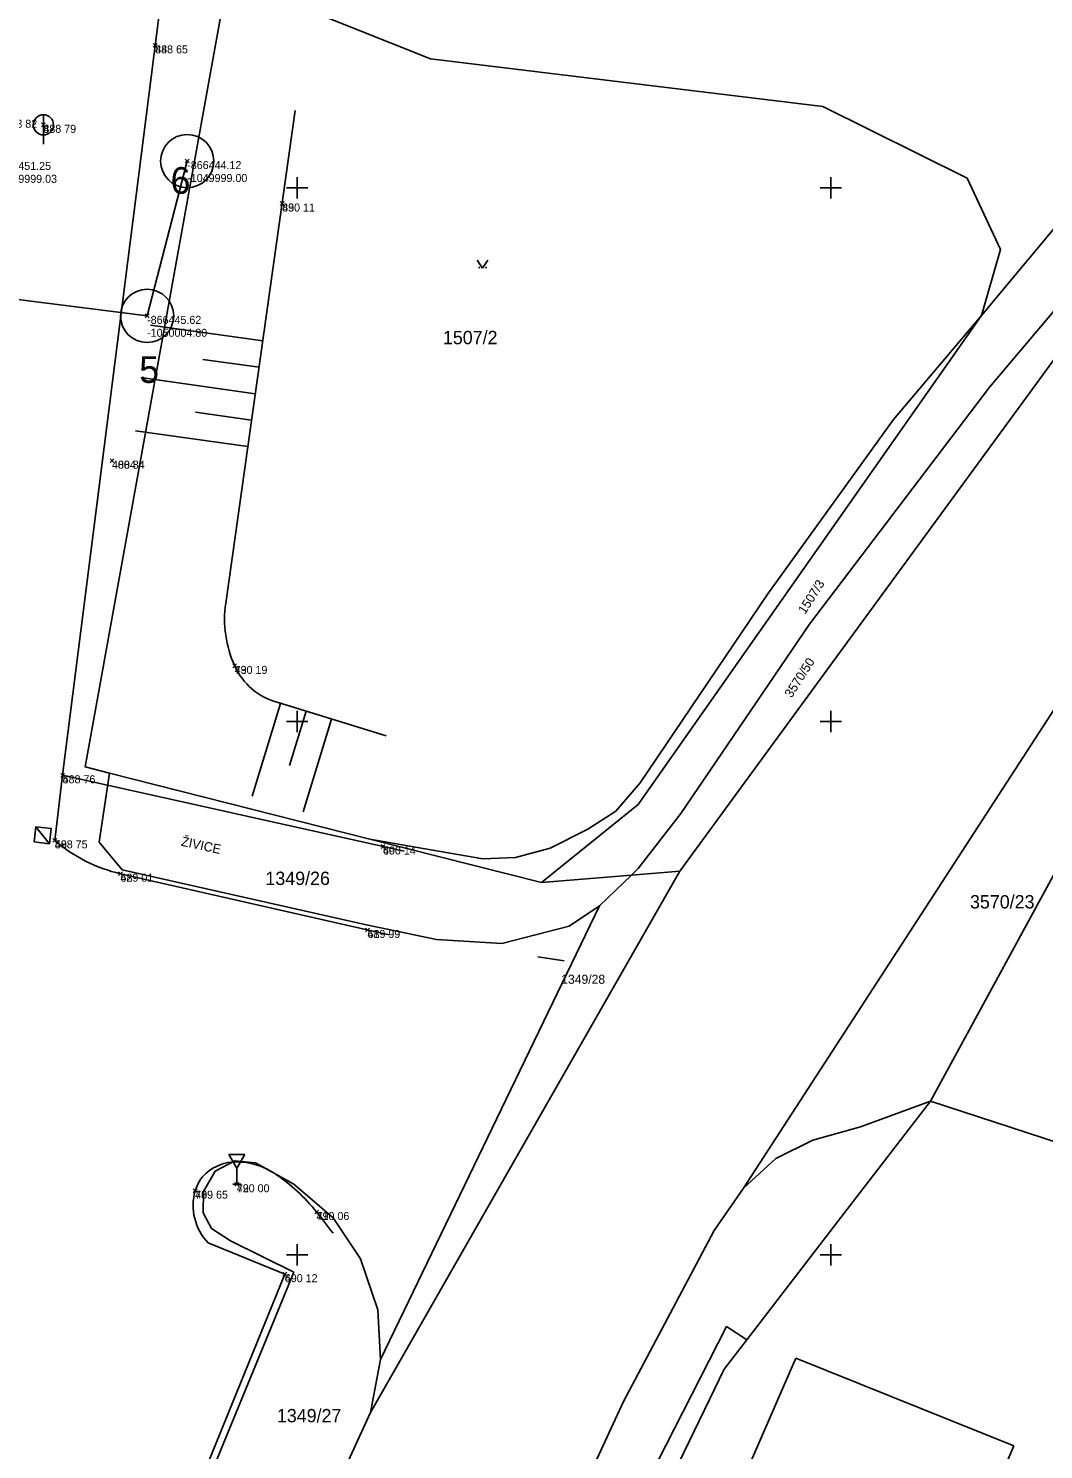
# Model space of a CAD drawing. Extents: x -866624 to -866276, y -1050208 to -1049940.
# Drawn here: x -866450.1 to -866412, y -1050047.3 to -1049994 of the extents above; entities that cross this region are included whole.
import ezdxf

# ---------------------------------------------------------------- set-up
doc = ezdxf.new("R2010")
doc.units = 0
for name, color, linetype in [('00_BODY VYTYČ', 7, 'Continuous'), ('00_POMOCNÉ KCE', 7, 'Continuous'), ('_FORMATY', 7, 'Continuous'), ('bod-cislo', 7, 'Continuous'), ('bod-oznac', 7, 'Continuous'), ('bod-vyska', 7, 'Continuous'), ('CTV-SIT', 7, 'Continuous'), ('Default', 7, 'Continuous'), ('DOPR-ZAR', 7, 'Continuous'), ('HRAN-LIN', 7, 'Continuous'), ('Hranice', 7, 'Continuous'), ('Hranice-budov', 7, 'Continuous'), ('Parcela-pozemkova', 7, 'Continuous'), ('Parcelni-cisla-pomocna', 7, 'Continuous'), ('POTR-ZAR', 7, 'Continuous'), ('SIT_05_NÁVRH PLYN', 7, 'Continuous'), ('TEXT', 7, 'Continuous'), ('VYS-SRAF', 7, 'Continuous'), ('Znacky-kultury', 7, 'Continuous')]:
    doc.layers.add(name, color=color, linetype=linetype)

# ---------------------------------------------------------------- blocks, each defined once
blk = doc.blocks.new('p_park')
at = {"layer": 'Default'}
for p, q in [((-1, 1.5), (0, 0)), ((0, 0), (1, 1.5))]:
    blk.add_line(p, q, dxfattribs=at)
for centre, start, end in [((-0.62, 0.1), 360, 180), ((-0.62, 0.1), 180, 360), ((0.66, 0.1), 0, 180), ((0.66, 0.1), 180, 0)]:
    blk.add_arc(centre, 0.05, start, end, dxfattribs=at)
blk = doc.blocks.new('POINT_DISPLAY')
at = {"layer": 'Default'}
for p, q in [((-0.071, 0.071), (0.071, -0.071)), ((0.071, 0.071), (-0.071, -0.071))]:
    blk.add_line(p, q, dxfattribs=at)
blk = doc.blocks.new('200RS')
at = {"layer": 'POTR-ZAR'}
blk.add_line((0, -0.378), (0, 0.721), dxfattribs=at)
blk.add_circle((0, 0), 0.378, dxfattribs=at)
blk = doc.blocks.new('200DZ')
at = {"layer": 'DOPR-ZAR'}
for p, q in [((-0.149, 0), (0.149, 0)), ((0, -0.599), (0, 0)), ((-0.3, -1.119), (0, -0.599)), ((0, -0.599), (0.3, -1.119)), ((0, -1.119), (-0.3, -1.119)), ((0.3, -1.119), (0, -1.119))]:
    blk.add_line(p, q, dxfattribs=at)
blk = doc.blocks.new('200UV')
at = {"layer": 'POTR-ZAR'}
for p, q in [((-0.288, 0.288), (0.288, -0.288)), ((0.288, 0.288), (-0.288, 0.288)), ((-0.288, 0.288), (-0.288, -0.288)), ((0.288, -0.288), (0.288, 0.288)), ((-0.288, -0.288), (0.288, -0.288))]:
    blk.add_line(p, q, dxfattribs=at)
blk.add_lwpolyline([(0.288, -0.288), (0.288, 0.288), (-0.288, 0.288)], close=True, dxfattribs=at)
blk = doc.blocks.new('CTVSIT')
at = {"layer": 'Default'}
for p, q in [((-2, 0), (2, 0)), ((0, 2), (0, -2))]:
    blk.add_line(p, q, dxfattribs=at)
blk = doc.blocks.new('vytyčení')
at = {"layer": '00_POMOCNÉ KCE'}
for centre in [(-866082.454, -1050060.072), (-866076.494, -1050060.691)]:
    blk.add_circle(centre, 0.998, dxfattribs=at)
at = {"layer": 'SIT_05_NÁVRH PLYN'}
blk.add_lwpolyline([(-866082.454, -1050060.072), (-866076.494, -1050060.691), (-866076.292, -1050069.077)], dxfattribs=at)

msp = doc.modelspace()

# ---------------------------------------------------------------- linework, layer by layer
at = {"layer": '_FORMATY'}
msp.add_line((-866429.993, -1050028.98), (-866430.982, -1050028.83), dxfattribs=at)
at = {"layer": 'HRAN-LIN'}
for p, q in [((-866445.172, -1049993.49), (-866448.79, -1050022.02)), ((-866448.79, -1050022.02), (-866449.08, -1050024.46)), ((-866435.988, -1050024.866), (-866448.79, -1050022.02)), ((-866444.8, -1050051.37), (-866440.46, -1050040.72))]:
    msp.add_line(p, q, dxfattribs=at)
for points in [[(-866440.067, -1049997.099), (-866442.677, -1050015.573)], [(-866440.752, -1050019.284), (-866436.662, -1050020.539)], [(-866436.55, -1050028.005), (-866446.62, -1050025.71)], [(-866443.331, -1050039.55), (-866440.46, -1050040.72)]]:
    msp.add_lwpolyline(points, dxfattribs=at)
for centre, radius, start, end in [((-866438.471, -1050016.167), 4.248, 171.9578, 204.3767), ((-866440.08, -1050016.896), 2.481, 204.3767, 254.2803), ((-866445.362, -1050020.188), 5.663, 228.9634, 257.1636), ((-866442.291, -1050038.193), 1.682, 90.054, 131.4076), ((-866442.291, -1050039.129), 2.617, 56.3463, 90.054), ((-866442.485, -1050037.974), 1.389, 131.4076, 163.9666), ((-866444.667, -1050042.698), 6.906, 38.5998, 56.3463), ((-866441.881, -1050038.147), 2.017, 163.9666, 224.0612), ((-866467.78, -1050061.149), 36.48, 37.0215, 38.5998)]:
    msp.add_arc(centre, radius, start, end, dxfattribs=at)
at = {"layer": 'Hranice'}
for p, q in [((-866447.95, -1050021.71), (-866442.6, -1049992.13)), ((-866442.6, -1049992.13), (-866435, -1049995.17)), ((-866425.65, -1050025.61), (-866402.57, -1049994.04)), ((-866435, -1049995.17), (-866420.29, -1049996.95)), ((-866406.93, -1049995.89), (-866414.35, -1050004.79)), ((-866420.29, -1049996.95), (-866414.88, -1049999.64)), ((-866414.88, -1049999.64), (-866413.64, -1050002.31)), ((-866408.09, -1050000.42), (-866414.04, -1050007.46)), ((-866414.35, -1050004.79), (-866413.64, -1050002.31)), ((-866427.22, -1050023.12), (-866414.35, -1050004.79)), ((-866417.65, -1050008.69), (-866414.35, -1050004.79)), ((-866414.04, -1050007.46), (-866420.79, -1050016.36)), ((-866422.35, -1050015.22), (-866417.65, -1050008.69)), ((-866427.14, -1050022.31), (-866422.35, -1050015.22)), ((-866420.79, -1050016.36), (-866425.62, -1050023.45)), ((-866423.27, -1050037.5), (-866409.54, -1050016.33)), ((-866447.03, -1050021.94), (-866447.95, -1050021.71)), ((-866447.03, -1050021.94), (-866447.42, -1050024.53)), ((-866437.27, -1050024.41), (-866447.03, -1050021.94)), ((-866428.05, -1050023.37), (-866427.14, -1050022.31)), ((-866430.84, -1050026.04), (-866427.22, -1050023.12)), ((-866429.1, -1050024.04), (-866428.05, -1050023.37)), ((-866427.22, -1050025.52), (-866425.62, -1050023.45)), ((-866410.49, -1050023.63), (-866416.26, -1050034.23)), ((-866437.27, -1050024.41), (-866435.56, -1050024.71)), ((-866437.27, -1050024.41), (-866430.84, -1050026.04)), ((-866430.52, -1050024.75), (-866429.1, -1050024.04)), ((-866446.56, -1050025.56), (-866447.42, -1050024.53)), ((-866435.56, -1050024.71), (-866433.04, -1050025.15)), ((-866431.81, -1050025.1), (-866430.52, -1050024.75)), ((-866437.46, -1050027.61), (-866446.56, -1050025.56)), ((-866433.04, -1050025.15), (-866431.81, -1050025.1)), ((-866427.47, -1050025.76), (-866427.22, -1050025.52)), ((-866437.25, -1050045.91), (-866425.65, -1050025.61)), ((-866430.84, -1050026.04), (-866427.47, -1050025.76)), ((-866428.67, -1050026.92), (-866427.47, -1050025.76)), ((-866427.47, -1050025.76), (-866425.65, -1050025.61)), ((-866428.67, -1050026.92), (-866436.87, -1050043.92)), ((-866428.67, -1050026.92), (-866429.8, -1050027.68)), ((-866434.78, -1050028.18), (-866437.46, -1050027.61)), ((-866429.8, -1050027.68), (-866432.32, -1050028.33)), ((-866432.32, -1050028.33), (-866434.78, -1050028.18)), ((-866419.49, -1050038.43), (-866416.26, -1050034.23)), ((-866416.26, -1050034.23), (-866418.88, -1050035.2)), ((-866416.26, -1050034.23), (-866404.22, -1050038.17)), ((-866420.67, -1050035.7), (-866422.06, -1050036.38)), ((-866418.88, -1050035.2), (-866420.67, -1050035.7)), ((-866442.34, -1050036.47), (-866443.07, -1050036.86)), ((-866441.56, -1050036.55), (-866442.34, -1050036.47)), ((-866440.12, -1050037.35), (-866441.56, -1050036.55)), ((-866423.27, -1050037.5), (-866422.06, -1050036.38)), ((-866443.07, -1050036.86), (-866443.51, -1050037.62)), ((-866443.51, -1050037.62), (-866443.52, -1050038.42)), ((-866438.65, -1050038.61), (-866440.12, -1050037.35)), ((-866423.27, -1050037.5), (-866424.37, -1050039.08)), ((-866443.52, -1050038.42), (-866443.21, -1050039.01)), ((-866437.62, -1050040.15), (-866438.65, -1050038.61)), ((-866423.14, -1050043.18), (-866419.49, -1050038.43)), ((-866443.21, -1050039.01), (-866442.5, -1050039.47)), ((-866424.37, -1050039.08), (-866427.77, -1050045.49)), ((-866442.5, -1050039.47), (-866440.12, -1050040.65)), ((-866436.98, -1050042.06), (-866437.62, -1050040.15)), ((-866444.5, -1050051.29), (-866440.12, -1050040.65)), ((-866436.87, -1050043.92), (-866436.98, -1050042.06)), ((-866423.91, -1050042.68), (-866426.83, -1050048.41)), ((-866423.91, -1050042.68), (-866423.14, -1050043.18)), ((-866423.14, -1050043.18), (-866423.99, -1050044.28)), ((-866436.87, -1050043.92), (-866437.25, -1050045.91)), ((-866421.31, -1050043.87), (-866426.27, -1050055.25)), ((-866421.31, -1050043.87), (-866413.14, -1050047.15)), ((-866428.8, -1050054.23), (-866423.99, -1050044.28)), ((-866431.86, -1050054.39), (-866427.77, -1050045.49)), ((-866437.25, -1050045.91), (-866439, -1050049.72)), ((-866413.14, -1050047.15), (-866414.06, -1050049.31))]:
    msp.add_line(p, q, dxfattribs=at)
at = {"layer": 'Hranice-budov'}
for p, q in [((-866421.31, -1050043.87), (-866426.27, -1050055.25)), ((-866421.31, -1050043.87), (-866413.14, -1050047.15)), ((-866413.14, -1050047.15), (-866414.06, -1050049.31))]:
    msp.add_line(p, q, dxfattribs=at)
at = {"layer": 'VYS-SRAF'}
for p, q in [((-866445.493, -1050005.146), (-866441.288, -1050005.74)), ((-866443.53, -1050006.433), (-866441.428, -1050006.73)), ((-866445.773, -1050007.126), (-866441.567, -1050007.72)), ((-866443.81, -1050008.413), (-866441.707, -1050008.71)), ((-866446.053, -1050009.106), (-866441.847, -1050009.701)), ((-866440.619, -1050019.325), (-866441.688, -1050022.809)), ((-866439.663, -1050019.619), (-866440.286, -1050021.649)), ((-866438.707, -1050019.912), (-866439.776, -1050023.396))]:
    msp.add_line(p, q, dxfattribs=at)

# ---------------------------------------------------------------- block references
at = {"layer": '00_BODY VYTYČ'}
for p in [(-866444.119, -1049999), (-866445.622, -1050004.801)]:
    msp.add_blockref('POINT_DISPLAY', p, dxfattribs=at)
at = {"layer": '00_POMOCNÉ KCE', "rotation": -98.59344504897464}
msp.add_blockref('vytyčení', (42415.469, -2063260.675), dxfattribs=at)
at = {"layer": '00_POMOCNÉ KCE'}
for p in [(-866444.119, -1049999), (-866445.622, -1050004.801)]:
    msp.add_blockref('POINT_DISPLAY', p, dxfattribs=at)
at = {"layer": 'bod-oznac'}
for p in [(-866445.32, -1049994.66), (-866449.51, -1049997.64), (-866440.56, -1050000.59), (-866446.94, -1050010.23), (-866442.34, -1050017.92), (-866448.79, -1050022.02), (-866449.08, -1050024.46), (-866436.78, -1050024.69), (-866446.62, -1050025.71), (-866437.36, -1050027.82), (-866442.26, -1050037.35), (-866443.82, -1050037.59), (-866439.27, -1050038.39), (-866440.46, -1050040.72)]:
    msp.add_blockref('POINT_DISPLAY', p, dxfattribs=at)
at = {"layer": 'CTV-SIT', "xscale": 0.19999999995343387, "yscale": 0.19999999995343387}
for p in [(-866440, -1050000), (-866420, -1050000), (-866440, -1050020), (-866420, -1050020), (-866440, -1050040), (-866420, -1050040)]:
    msp.add_blockref('CTVSIT', p, dxfattribs=at)
at = {"layer": 'DOPR-ZAR', "rotation": 179.99999999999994}
msp.add_blockref('200DZ', (-866442.26, -1050037.35), dxfattribs=at)
at = {"layer": 'POTR-ZAR'}
for name, p, rotation in [('200RS', (-866449.51, -1049997.64), 179.99999999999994), ('200UV', (-866449.537, -1050024.269), -6.777948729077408)]:
    msp.add_blockref(name, p, dxfattribs=dict(at, rotation=rotation))
at = {"layer": 'Znacky-kultury', "xscale": 0.2, "yscale": 0.20000000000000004}
msp.add_blockref('p_park', (-866433.05, -1050003.01), dxfattribs=at)

# ---------------------------------------------------------------- texts
at = {"layer": '00_BODY VYTYČ'}
for s, p in [('6', (-866444.742, -1050000.225)), ('5', (-866445.918, -1050007.314))]:
    msp.add_text(s, height=1, dxfattribs=at).set_placement(p)
at = {"layer": '00_POMOCNÉ KCE'}
for s, p in [('-866451.25', (-866451.253, -1049999.331)), ('-866444.12', (-866444.119, -1049999.3)), ('-1049999.00', (-866444.119, -1049999.784)), ('-1049999.03', (-866451.253, -1049999.814)), ('-866445.62', (-866445.622, -1050005.101)), ('-1050004.80', (-866445.622, -1050005.585))]:
    msp.add_text(s, height=0.3, dxfattribs=at).set_placement(p)
at = {"layer": 'bod-cislo'}
for s, p in [('84', (-866445.32, -1049994.96)), ('83', (-866449.51, -1049997.94)), ('85', (-866440.56, -1050000.89)), ('4004', (-866446.94, -1050010.53)), ('73', (-866442.34, -1050018.22)), ('58', (-866448.79, -1050022.32)), ('59', (-866449.08, -1050024.76)), ('60', (-866436.78, -1050024.99)), ('62', (-866446.62, -1050026.01)), ('61', (-866437.36, -1050028.12)), ('70', (-866443.82, -1050037.89)), ('72', (-866442.26, -1050037.65)), ('71', (-866439.27, -1050038.69)), ('69', (-866440.46, -1050041.02))]:
    msp.add_text(s, height=0.3, dxfattribs=at).set_placement(p)
at = {"layer": 'bod-vyska'}
for s, p in [('488 65', (-866445.32, -1049994.96)), ('488 82', (-866450.97, -1049997.75)), ('488 79', (-866449.51, -1049997.94)), ('490 11', (-866440.56, -1050000.89)), ('488 84', (-866446.94, -1050010.53)), ('490 19', (-866442.34, -1050018.22)), ('488 76', (-866448.79, -1050022.32)), ('488 75', (-866449.08, -1050024.76)), ('490 14', (-866436.78, -1050024.99)), ('489 01', (-866446.62, -1050026.01)), ('489 99', (-866437.36, -1050028.12)), ('489 65', (-866443.82, -1050037.89)), ('490 00', (-866442.26, -1050037.65)), ('490 06', (-866439.27, -1050038.69)), ('490 12', (-866440.46, -1050041.02))]:
    msp.add_text(s, height=0.3, dxfattribs=at).set_placement(p)
at = {"layer": 'Parcela-pozemkova'}
for s, p in [('1507/2', (-866434.534, -1050005.863)), ('1349/26', (-866441.187, -1050026.133)), ('3570/23', (-866414.777, -1050027.013)), ('1349/27', (-866440.757, -1050046.273))]:
    msp.add_text(s, height=0.5, dxfattribs=at).set_placement(p)
at = {"layer": 'Parcelni-cisla-pomocna'}
for s, p in [('1507/3', (-866420.959, -1050016.005)), ('3570/50', (-866421.466, -1050019.143))]:
    msp.add_text(s, height=0.34, rotation=57.3908, dxfattribs=at).set_placement(p)
msp.add_text('1349/28', height=0.34, dxfattribs=at).set_placement((-866430.099, -1050029.836))
at = {"layer": 'TEXT'}
msp.add_text('ŽIVICE', height=0.35, rotation=347.8798, dxfattribs=at).set_placement((-866444.369, -1050024.657))

doc.saveas('drawing.dxf')
